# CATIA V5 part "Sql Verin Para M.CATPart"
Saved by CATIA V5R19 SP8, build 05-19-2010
Part number: Sql Verin Para M
Publications: "Droite.1", "Point.3", "Plan.1"
Bounding box of the stored display mesh (mm): x 0 to 0, y -120 to 470, z -700 to -425
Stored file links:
  G:\EU_thinkMotion\CFAO_2010\MMS_groupe3\MMS_groupe3\rdalborgo\rdalborgo\Sql Verin Para M.CATPart
  G:\EU_thinkMotion\CFAO_2010\MMS_groupe3\MMS_groupe3\rdalborgo\rdalborgo\rdalborgo.CATProduct
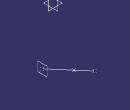
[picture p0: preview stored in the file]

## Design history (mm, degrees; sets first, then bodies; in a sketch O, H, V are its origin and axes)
Set1
  Point1 "B verin para": linked copy from another document
  Point2 "A verin para": linked copy from another document
  Plane1: linked copy from another document
Set2
  Line1: type PtPt, FirstPoint Point1, SecondPoint Point2
  Point3: type OnCurve, Support Line1, Ratio 0.6
  Plane2: type OffsetPt, RefPlane Plane1, RefPoint Point1
Body1 (main body)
